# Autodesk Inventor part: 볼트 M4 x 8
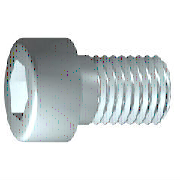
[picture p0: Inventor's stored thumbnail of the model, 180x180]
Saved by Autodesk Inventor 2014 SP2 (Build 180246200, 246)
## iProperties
IsCustomPart: 0
Created: 2012-02
Part Number: 볼트 M4 x 8
Material: 스테인리스강
Description: 6각 소켓 머리 캡 나사
Document SubType Name: Modeling
Standard: ISO 4762
Designer: mduedu
Standard Revision: Fourth edition 2004-03-01
Standards Organization: ISO
Language: ko-KR
Size Designation: M4 x 8
Categories: <MemberInstance><Categories><Category DisplayName="조임쇠" InternalName="e4da775c-781d-43d5-af7c-5136215cf5a6" Mnemonic="FSTN"><Category DisplayName="볼트" InternalN
Density: 7.75 g/cm^3
Appearance: 반광택
Author: mduedu
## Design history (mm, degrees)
sketch "스케치1"
  geometry: L1 (-1, 0)-(8, 0); L2 (8, 0)-(8, 2); L3 (8, 2)-(1.75, 2); L4 (1.75, 2)-(1.32, 2); L5 (1.32, 2)-(0, 2); L6 (0, 2)-(0, 3.5); L7 (0, 3.5)-(-4, 3.5); L8 (-4, 3.5)-(-4, 1.732); L9 (-4, 1.732)-(-2, 1.732); L10 (-2, 1.732)-(-1, 0); L11 (-6.4, 0)-(10.4, 0) reference; L12 (0, -0.7)-(0, 4.2) reference; L13 (1.75, 2)-(0, 2)
  constraints: 22 end point, 6 parallel, 2 collinear, 2 perpendicular, 1 horizontal, 1 point on line
  dimensions: "d1" = 6.25 distance from line of L3.end L2 (= GEL); "d2" = 0.42952 distance of L4.end L3.end (computed from GAL); "d3" = 4 distance between parallel lines of L8 L6 (= KOH); "d4" = 2 distance of L8.end L9.end (= INTI); "d5" = 60 deg angle of L10 L1; "d6" = 4 diameter of L3 L1 (= GD); "d7" = 4 diameter of L5 L1 (= BDM); "d8" = 3.4641 diameter of L9 L1 (= 1.1547 x SW); "d9" = 7 diameter of L7 L1 (= KOD); "d26" = 8 distance between parallel lines of L12 L2 (= NLG)
revolve "본체" sketch "스케치1" stored, may be unused: angle "d10" = 90 deg
sketch "스케치2"
  geometry: L1 (0, -4.9)-(0, 4.9) reference; L2 (-4.9, 0)-(4.9, 0) reference; L3 (1.732, 0)-(0.866, -1.5); L4 (0.866, -1.5)-(-0.866, -1.5); L5 (-0.866, -1.5)-(-1.732, 0); L6 (-1.732, 0)-(-0.866, 1.5); L7 (-0.866, 1.5)-(0.866, 1.5); L8 (0.866, 1.5)-(1.732, 0); 2 further points
  constraints: 12 end point, 1 coincident, 1 horizontal alignment, 1 point on line, 12 other
extrude "슬롯" join sketch "스케치2" stored distance "d11" = 10; taper "d12" = 0 deg
workplane "Work Plane1"
fillet "Fillet2" dims "d30" = 0.1 (= R)
body "Solid1"
fillet "모깎기1" dims "d17" = 0.4 (= RR)
feature "스레드" dims "d13" = 6.25 (= GEL), "d14" = 0
chamfer "모따기1" distance "d15" = 0.42941 (= -0.5 x SPD + 0.5 x GD); stored, may be unused: second distance "d16" = 0.42941 (= GUL), angle "d27" = 45 deg
other parameters: "GD" = 4 [user parameter; used in 2 equation terms], "NLG" = 8 [user parameter; used in 1 equation term], "GEL" = 6.25 [user parameter; used in 2 equation terms], "KOD" = 7 [user parameter; used in 1 equation term], "KOH" = 4 [user parameter; used in 1 equation term], "INTI" = 2 [user parameter; used in 1 equation term], "GAL" = 0.42941 (= 0.61345 x PTC) [user parameter; used in 1 equation term], "GUL" = 0.42941 (= 0.61345 x PTC) [user parameter; used in 1 equation term], "BDM" = 4 (= NND) [user parameter; used in 1 equation term], "SW" = 3 [user parameter; used in 2 equation terms], "RR" = 0.4 [user parameter; used in 1 equation term], "SPD" = 3.14117 (= NND - 1.2269 x PTC) [user parameter; used in 1 equation term], "d19" = 0, "d28" = 0, "d29" = 0, "R" = 0.1 [user parameter; used in 1 equation term], "TOA" = 30 deg [user parameter], "GD1" = 3.14117 (= THREADDIA - 1.2269 x PTC) [user parameter], "THREADDIA" = 4 [user parameter; used in 1 equation term], "FAWI" = 45 deg [user parameter], "TPU" = 14.28571 (computed from PTC) [user parameter], "PTC" = 0.7 [user parameter; used in 5 equation terms], "NND" = 4 [user parameter; used in 2 equation terms], "E0" = 3.465 (= 1.155 x SW) [user parameter]
